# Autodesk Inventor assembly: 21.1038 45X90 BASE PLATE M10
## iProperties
Created: 2007-03
Part Number: 21.1038 45X90 BASE PLATE M10
Document SubType Name: Assembly
Designer: Andy Moles
Author: Andy Moles
